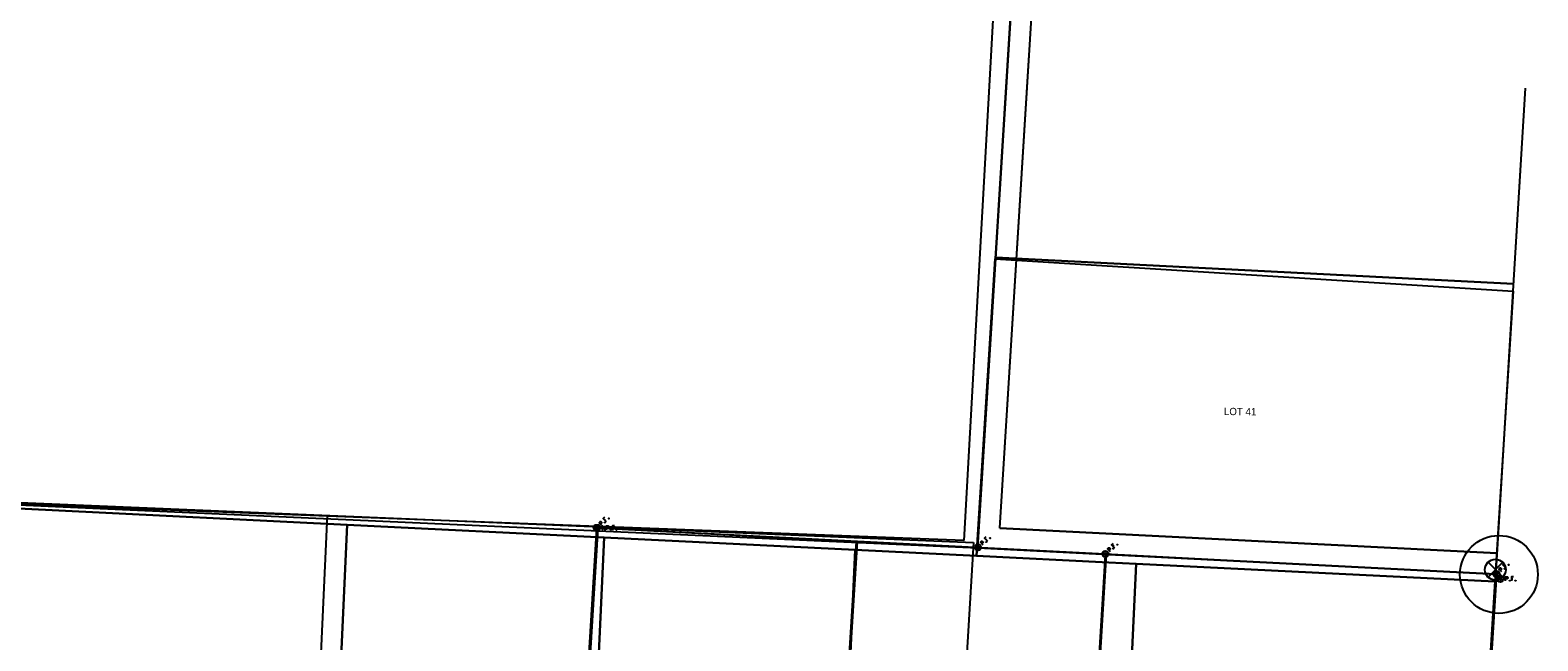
# Model space of a CAD drawing. Extents: x 1532954 to 1577849, y 698998 to 706606.
# Drawn here: x 1572810 to 1573391, y 703345 to 703581 of the extents above; entities that cross this region are included whole.
import ezdxf

# ---------------------------------------------------------------- set-up
doc = ezdxf.new("R2010")
doc.units = 0
for name, color, linetype in [('Default', 7, 'Continuous'), ('DV_X_Property_Line', 7, 'Continuous'), ('RW_X_Esmt_U', 7, 'Continuous'), ('RW_X_Fee_RW', 7, 'Continuous'), ('SC_Scratch1', 7, 'Continuous'), ('SC_Scratch2', 7, 'Continuous'), ('SC_Scratch3', 7, 'Continuous'), ('SC_Scratch4', 7, 'Continuous'), ('SC_Scratch9', 7, 'Continuous'), ('SV_X_Mon_Cells_Found', 7, 'Continuous')]:
    doc.layers.add(name, color=color, linetype=linetype)

msp = doc.modelspace()

# ---------------------------------------------------------------- linework, layer by layer
at = {"layer": 'Default'}
for p, q in [((1573371.66, 703375.68), (1573377.31, 703370.02)), ((1573371.66, 703370.02), (1573377.31, 703375.68)), ((1573374.48, 703372.85), (1573374.48, 703372.85))]:
    msp.add_line(p, q, dxfattribs=at)
msp.add_circle((1573374.48, 703372.85), 4, dxfattribs=at)
at = {"layer": 'DV_X_Property_Line'}
for p, q in [((1573175.06, 703381.24), (1573203.31, 703834.11)), ((1573182.03, 703493.03), (1573381.49, 703482.97)), ((1572699.41, 703402.55), (1573175.06, 703381.24)), ((1572907.39, 703018.94), (1572924.6, 703393.96)), ((1573006.97, 703032.51), (1573028.82, 703388.75)), ((1573108.02, 703046.29), (1573128.72, 703383.76)), ((1573175.06, 703381.24), (1573374.69, 703371.17)), ((1573205.13, 703059.52), (1573224.73, 703378.97))]:
    msp.add_line(p, q, dxfattribs=at)
at = {"layer": 'RW_X_Esmt_U'}
for q in [(1573194.92, 703571.06), (1573375.09, 703379.16)]:
    msp.add_line((1573183.55, 703388.82), q, dxfattribs=at)
at = {"layer": 'RW_X_Fee_RW'}
msp.add_line((1573356.99, 703080.22), (1573386.06, 703558.24), dxfattribs=at)
at = {"layer": 'SC_Scratch1'}
msp.add_lwpolyline([(1572244.56, 703864.45), (1573202.26, 703819.91), (1573195.75, 703716.12), (1573195.75, 703716.12), (1573188.75, 703604.34), (1573188.75, 703604.34), (1573181.74, 703492.56), (1573181.74, 703492.56), (1573174.57, 703378.16), (1573127.9, 703380.47), (1573031.18, 703385.25), (1572932.18, 703390.15), (1572818.4, 703395.78), (1572706.35, 703401.33), (1572701.55, 703298.03), (1572689.2, 703032.48), (1572687.31, 702991.85), (1572375.87, 702949.15)], dxfattribs=at)
for points in [[(1573381.35, 703480.05), (1573374.34, 703368.27), (1573236.04, 703375.12), (1573225.57, 703375.64), (1573174.57, 703378.16), (1573181.74, 703492.56)], [(1572932.18, 703390.15), (1572927.2, 703283.07), (1572917, 703063.72), (1572915.11, 703023.08), (1572800.34, 703007.35), (1572687.31, 702991.85), (1572689.2, 703032.48), (1572701.55, 703298.03), (1572706.35, 703401.33), (1572818.4, 703395.78)], [(1573031.18, 703385.25), (1573026.13, 703276.51), (1573016.87, 703077.41), (1573014.98, 703036.77), (1572964.59, 703029.87), (1572915.11, 703023.08), (1572917, 703063.72), (1572927.2, 703283.07), (1572932.18, 703390.15)], [(1573127.9, 703380.47), (1573122.77, 703270.11), (1573114.43, 703090.78), (1573112.54, 703050.15), (1573014.98, 703036.77), (1573016.87, 703077.41), (1573026.13, 703276.51), (1573031.18, 703385.25)], [(1573174.57, 703378.16), (1573225.57, 703375.64), (1573236.04, 703375.12), (1573223.52, 703105.74), (1573221.63, 703065.11), (1573207.45, 703063.17), (1573112.54, 703050.15), (1573114.43, 703090.78), (1573122.77, 703270.11), (1573127.9, 703380.47)], [(1573359.05, 703124.32), (1573384.32, 703127.79), (1573381.77, 703087.06), (1573356.5, 703083.6), (1573221.63, 703065.11), (1573223.52, 703105.74), (1573236.04, 703375.12), (1573374.34, 703368.27)]]:
    msp.add_lwpolyline(points, close=True, dxfattribs=at)
at = {"layer": 'SC_Scratch2'}
for p, q in [((1573175.06, 703381.24), (1573302, 705416.24)), ((1573183.55, 703388.82), (1573309.47, 705407.5)), ((1573194.95, 703837.12), (1573169.65, 703384.08)), ((1573356.99, 703080.23), (1573386.06, 703558.24)), ((1573381.49, 703482.97), (1573182.03, 703493.03)), ((1573169.65, 703384.08), (1572695.63, 703402.26)), ((1573006.3, 703032.86), (1573028.3, 703388.98)), ((1573028.3, 703388.98), (1573128.16, 703383.68)), ((1573375.09, 703379.16), (1573183.55, 703388.82)), ((1573128.16, 703383.68), (1573107.32, 703046.43)), ((1573374.69, 703371.17), (1573175.06, 703381.24))]:
    msp.add_line(p, q, dxfattribs=at)
for points in [[(1573030.3, 703388.16), (1573030.65, 703388.16)], [(1573030.32, 703389.76), (1573030.67, 703389.75)], [(1573030.48, 703388.16), (1573030.49, 703389.76)], [(1573031.44, 703388.36), (1573031.49, 703388.36), (1573031.53, 703388.34), (1573031.56, 703388.28), (1573031.56, 703388.22), (1573031.53, 703388.17), (1573031.49, 703388.15), (1573031.44, 703388.15), (1573031.4, 703388.17), (1573031.37, 703388.22), (1573031.37, 703388.29), (1573031.41, 703388.34), (1573031.44, 703388.36)], [(1573032.04, 703388.14), (1573032.06, 703389.74), (1573032.59, 703389.74), (1573032.64, 703389.72), (1573032.72, 703389.7), (1573032.75, 703389.67), (1573032.79, 703389.65), (1573032.83, 703389.58), (1573032.86, 703389.52), (1573032.88, 703389.42), (1573032.88, 703389.27), (1573032.87, 703389.22), (1573032.85, 703389.14), (1573032.8, 703389.05), (1573032.76, 703389.02), (1573032.72, 703388.99), (1573032.67, 703388.97), (1573032.58, 703388.96), (1573032.05, 703388.96)], [(1573033.69, 703388.34), (1573033.74, 703388.34), (1573033.78, 703388.31), (1573033.81, 703388.26), (1573033.81, 703388.2), (1573033.77, 703388.15), (1573033.74, 703388.13), (1573033.69, 703388.13), (1573033.65, 703388.15), (1573033.62, 703388.2), (1573033.62, 703388.27), (1573033.65, 703388.32), (1573033.69, 703388.34)], [(1573035.07, 703389.71), (1573034.31, 703389.72), (1573034.29, 703388.12)], [(1573034.3, 703388.94), (1573034.84, 703388.93)], [(1573035.84, 703388.32), (1573035.89, 703388.32), (1573035.93, 703388.29), (1573035.96, 703388.24), (1573035.96, 703388.18), (1573035.92, 703388.13), (1573035.89, 703388.1), (1573035.84, 703388.11), (1573035.8, 703388.13), (1573035.77, 703388.18), (1573035.77, 703388.24), (1573035.8, 703388.29), (1573035.84, 703388.32)]]:
    msp.add_lwpolyline(points, dxfattribs=at)
msp.add_circle((1573028.3, 703388.98), 1.2, dxfattribs=at)
at = {"layer": 'SC_Scratch3'}
for p, q in [((1572699.49, 703403.12), (1573173.45, 703383.28)), ((1573173.45, 703383.28), (1573153.38, 703054.89))]:
    msp.add_line(p, q, dxfattribs=at)
at = {"layer": 'SC_Scratch4'}
for p, q in [((1573006.23, 703032.86), (1573028.3, 703388.98)), ((1573028.3, 703388.98), (1573224.18, 703378.9)), ((1573224.15, 703378.38), (1573204.41, 703059.79)), ((1573224.18, 703378.9), (1573374.94, 703371.14)), ((1573374.95, 703371.15), (1573356.94, 703080.51))]:
    msp.add_line(p, q, dxfattribs=at)
for points in [[(1573030.28, 703389.8), (1573029.16, 703390.95), (1573029.54, 703391.32), (1573029.59, 703391.35), (1573029.66, 703391.38), (1573029.7, 703391.39), (1573029.74, 703391.39), (1573029.82, 703391.38), (1573029.89, 703391.36), (1573029.97, 703391.3), (1573030.08, 703391.19), (1573030.11, 703391.15), (1573030.14, 703391.08), (1573030.17, 703390.99), (1573030.17, 703390.93), (1573030.16, 703390.89), (1573030.14, 703390.83), (1573030.09, 703390.76), (1573029.71, 703390.39)], [(1573031.31, 703393.05), (1573030.77, 703392.52), (1573031.89, 703391.38)], [(1573031.3, 703391.11), (1573031.34, 703391.15), (1573031.39, 703391.15), (1573031.44, 703391.14), (1573031.49, 703391.09), (1573031.5, 703391.03), (1573031.49, 703390.99), (1573031.45, 703390.95), (1573031.41, 703390.95), (1573031.35, 703390.96), (1573031.31, 703391.01), (1573031.3, 703391.07), (1573031.3, 703391.11)], [(1573031.31, 703391.96), (1573031.7, 703392.34)], [(1573032.84, 703392.61), (1573032.88, 703392.65), (1573032.92, 703392.66), (1573032.98, 703392.64), (1573033.02, 703392.6), (1573033.03, 703392.54), (1573033.03, 703392.5), (1573032.99, 703392.46), (1573032.95, 703392.45), (1573032.89, 703392.47), (1573032.84, 703392.51), (1573032.83, 703392.57), (1573032.84, 703392.61)], [(1573177.19, 703382.25), (1573176.07, 703383.39), (1573176.44, 703383.76), (1573176.49, 703383.79), (1573176.57, 703383.82), (1573176.61, 703383.83), (1573176.65, 703383.83), (1573176.72, 703383.82), (1573176.79, 703383.8), (1573176.88, 703383.74), (1573176.98, 703383.63), (1573177.01, 703383.59), (1573177.05, 703383.52), (1573177.08, 703383.43), (1573177.07, 703383.37), (1573177.07, 703383.33), (1573177.05, 703383.27), (1573176.99, 703383.2), (1573176.61, 703382.83)], [(1573178.22, 703385.49), (1573177.67, 703384.96), (1573178.79, 703383.82)], [(1573178.21, 703383.55), (1573178.25, 703383.59), (1573178.29, 703383.59), (1573178.35, 703383.58), (1573178.39, 703383.53), (1573178.41, 703383.47), (1573178.4, 703383.43), (1573178.36, 703383.4), (1573178.32, 703383.39), (1573178.26, 703383.4), (1573178.22, 703383.45), (1573178.2, 703383.51), (1573178.21, 703383.55)], [(1573178.22, 703384.4), (1573178.61, 703384.78)], [(1573179.74, 703385.05), (1573179.78, 703385.09), (1573179.83, 703385.1), (1573179.88, 703385.08), (1573179.93, 703385.04), (1573179.94, 703384.98), (1573179.93, 703384.94), (1573179.89, 703384.9), (1573179.85, 703384.89), (1573179.79, 703384.91), (1573179.75, 703384.95), (1573179.74, 703385.01), (1573179.74, 703385.05)], [(1573227.19, 703382.97), (1573226.65, 703382.44), (1573227.77, 703381.3)], [(1573227.19, 703381.88), (1573227.58, 703382.26)], [(1573228.72, 703382.53), (1573228.76, 703382.57), (1573228.8, 703382.58), (1573228.86, 703382.56), (1573228.9, 703382.52), (1573228.92, 703382.46), (1573228.91, 703382.42), (1573228.87, 703382.38), (1573228.83, 703382.37), (1573228.77, 703382.39), (1573228.73, 703382.43), (1573228.71, 703382.49), (1573228.72, 703382.53)], [(1573226.16, 703379.72), (1573225.04, 703380.87), (1573225.42, 703381.24), (1573225.47, 703381.27), (1573225.54, 703381.3), (1573225.58, 703381.31), (1573225.62, 703381.31), (1573225.7, 703381.3), (1573225.77, 703381.28), (1573225.85, 703381.22), (1573225.96, 703381.11), (1573225.99, 703381.07), (1573226.02, 703381), (1573226.05, 703380.91), (1573226.05, 703380.85), (1573226.04, 703380.81), (1573226.02, 703380.75), (1573225.97, 703380.68), (1573225.59, 703380.31)], [(1573227.19, 703381.03), (1573227.22, 703381.07), (1573227.27, 703381.07), (1573227.32, 703381.06), (1573227.37, 703381.01), (1573227.38, 703380.95), (1573227.37, 703380.91), (1573227.34, 703380.87), (1573227.29, 703380.87), (1573227.24, 703380.88), (1573227.19, 703380.93), (1573227.18, 703380.99), (1573227.19, 703381.03)], [(1573376.92, 703371.97), (1573375.8, 703373.11), (1573376.18, 703373.48), (1573376.23, 703373.51), (1573376.3, 703373.55), (1573376.34, 703373.55), (1573376.38, 703373.56), (1573376.46, 703373.54), (1573376.53, 703373.52), (1573376.61, 703373.46), (1573376.72, 703373.36), (1573376.75, 703373.31), (1573376.78, 703373.24), (1573376.81, 703373.15), (1573376.81, 703373.09), (1573376.8, 703373.05), (1573376.78, 703372.99), (1573376.73, 703372.92), (1573376.35, 703372.55)], [(1573377.95, 703375.22), (1573377.41, 703374.68), (1573378.53, 703373.54)], [(1573377.95, 703373.27), (1573377.99, 703373.31), (1573378.03, 703373.31), (1573378.09, 703373.3), (1573378.13, 703373.26), (1573378.14, 703373.2), (1573378.14, 703373.16), (1573378.1, 703373.12), (1573378.05, 703373.11), (1573378, 703373.12), (1573377.95, 703373.17), (1573377.94, 703373.23), (1573377.95, 703373.27)], [(1573377.96, 703374.13), (1573378.34, 703374.5)], [(1573379.48, 703374.77), (1573379.52, 703374.81), (1573379.56, 703374.82), (1573379.62, 703374.81), (1573379.66, 703374.76), (1573379.68, 703374.7), (1573379.67, 703374.66), (1573379.63, 703374.62), (1573379.59, 703374.62), (1573379.53, 703374.63), (1573379.49, 703374.67), (1573379.47, 703374.73), (1573379.48, 703374.77)]]:
    msp.add_lwpolyline(points, dxfattribs=at)
for centre, radius in [((1573028.3, 703388.98), 1.2), ((1573028.3, 703388.98), 0.495), ((1573175.2, 703381.42), 1.2), ((1573175.2, 703381.42), 0.495), ((1573224.18, 703378.9), 1.2), ((1573224.18, 703378.9), 0.495), ((1573374.94, 703371.14), 1.2), ((1573374.94, 703371.14), 0.495)]:
    msp.add_circle(centre, radius, dxfattribs=at)
at = {"layer": 'SC_Scratch9'}
msp.add_circle((1573375.86, 703371.01), 15, dxfattribs=at)
at = {"layer": 'SV_X_Mon_Cells_Found'}
for points in [[(1573378.41, 703368.49), (1573378.41, 703370.09), (1573378.94, 703370.09), (1573379, 703370.08), (1573379.07, 703370.05), (1573379.11, 703370.03), (1573379.14, 703370), (1573379.18, 703369.94), (1573379.22, 703369.88), (1573379.24, 703369.78), (1573379.24, 703369.62), (1573379.23, 703369.57), (1573379.21, 703369.5), (1573379.16, 703369.41), (1573379.12, 703369.37), (1573379.09, 703369.35), (1573379.03, 703369.32), (1573378.94, 703369.31), (1573378.41, 703369.31)], [(1573380.06, 703368.7), (1573380.11, 703368.7), (1573380.14, 703368.68), (1573380.18, 703368.63), (1573380.18, 703368.57), (1573380.14, 703368.52), (1573380.11, 703368.49), (1573380.06, 703368.49), (1573380.02, 703368.52), (1573379.99, 703368.57), (1573379.99, 703368.63), (1573380.02, 703368.68), (1573380.06, 703368.7)], [(1573381.42, 703370.09), (1573380.66, 703370.09), (1573380.66, 703368.49)], [(1573380.66, 703369.31), (1573381.2, 703369.31)], [(1573382.21, 703368.7), (1573382.26, 703368.7), (1573382.29, 703368.68), (1573382.33, 703368.63), (1573382.33, 703368.57), (1573382.29, 703368.52), (1573382.26, 703368.49), (1573382.21, 703368.49), (1573382.17, 703368.52), (1573382.14, 703368.57), (1573382.14, 703368.63), (1573382.17, 703368.68), (1573382.21, 703368.7)]]:
    msp.add_lwpolyline(points, dxfattribs=at)
for radius in [1.2, 0.495]:
    msp.add_circle((1573376.42, 703369.29), radius, dxfattribs=at)

# ---------------------------------------------------------------- texts
at = {"layer": 'SC_Scratch2'}
msp.add_text('LOT 41', height=2.8, rotation=359.4613, dxfattribs=at).set_placement((1573269.91, 703432.4))

doc.saveas('drawing.dxf')
